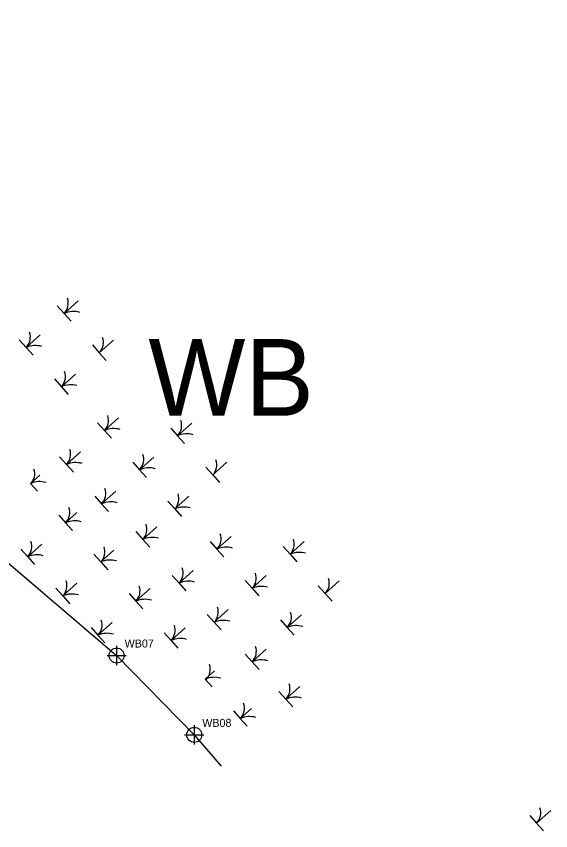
# Model space of a CAD drawing. Extents: x 2126502 to 2127032, y 149550 to 150101.
# Drawn here: x 2126748.5 to 2126915.4, y 149788.3 to 150042.6 of the extents above; entities that cross this region are included whole.
import ezdxf

# ---------------------------------------------------------------- set-up
doc = ezdxf.new("R2010")
doc.units = 0
for name, color, linetype in [('Default', 7, 'Continuous'), ('Exist Environmental Wetland Boundary', 7, 'Continuous'), ('Exist Environmental Wetland Boundary Cogo Number', 7, 'Continuous'), ('Exist Environmental Wetland Boundary Cogo Point CELL', 7, 'Continuous'), ('Exist Hydro Swamp or Marsh', 7, 'Continuous')]:
    doc.layers.add(name, color=color, linetype=linetype)

msp = doc.modelspace()

# ---------------------------------------------------------------- linework, layer by layer
at = {"layer": 'Exist Environmental Wetland Boundary'}
msp.add_lwpolyline([(2126558.24, 150042.64), (2126586.56, 150016.72), (2126627.79, 149984.18), (2126669.56, 149945.39), (2126708.19, 149909.19), (2126734.44, 149881.64), (2126779.81, 149842.99), (2126804.06, 149818.21), (2126812.44, 149808.38)], dxfattribs=at)
at = {"layer": 'Exist Environmental Wetland Boundary Cogo Point CELL'}
for points in [[(2126779.81, 149845.99), (2126779.81, 149842.99)], [(2126776.81, 149842.99), (2126779.81, 149842.99)], [(2126779.81, 149842.99), (2126782.81, 149842.99)], [(2126779.81, 149842.99), (2126779.81, 149839.99)], [(2126804.06, 149821.21), (2126804.06, 149818.21)], [(2126801.06, 149818.21), (2126804.06, 149818.21)], [(2126804.06, 149818.21), (2126807.06, 149818.21)], [(2126804.06, 149818.21), (2126804.06, 149815.21)]]:
    msp.add_lwpolyline(points, dxfattribs=at)
for centre in [(2126779.81, 149842.99), (2126804.06, 149818.21)]:
    msp.add_circle(centre, 2.34, dxfattribs=at)
at = {"layer": 'Exist Hydro Swamp or Marsh'}
for points in [[(2126761.27, 149952.23), (2126763.42, 149949.83), (2126767.83, 149953.78), (2126763.42, 149949.83), (2126765.57, 149947.42)], [(2126749.41, 149941.61), (2126751.56, 149939.21), (2126755.97, 149943.15), (2126751.56, 149939.21), (2126753.72, 149936.8)], [(2126772.24, 149939.98), (2126774.4, 149937.57), (2126778.8, 149941.52), (2126774.4, 149937.57), (2126776.55, 149935.17)], [(2126760.39, 149929.36), (2126762.54, 149926.95), (2126766.95, 149930.9), (2126762.54, 149926.95), (2126764.69, 149924.55)], [(2126773.85, 149915.67), (2126776, 149913.27), (2126780.41, 149917.22), (2126776, 149913.27), (2126778.16, 149910.87)], [(2126796.69, 149914.04), (2126798.84, 149911.64), (2126803.25, 149915.59), (2126798.84, 149911.64), (2126800.99, 149909.24)], [(2126762, 149905.05), (2126764.15, 149902.65), (2126768.56, 149906.6), (2126764.15, 149902.65), (2126766.3, 149900.25)], [(2126784.83, 149903.42), (2126786.98, 149901.02), (2126791.39, 149904.97), (2126786.98, 149901.02), (2126789.13, 149898.61)], [(2126807.66, 149901.79), (2126809.81, 149899.38), (2126814.22, 149903.33), (2126809.81, 149899.38), (2126811.97, 149896.98)], [(2126755.84, 149899.35), (2126752.9, 149896.71), (2126755.05, 149894.31)], [(2126772.97, 149892.8), (2126775.13, 149890.4), (2126779.53, 149894.34), (2126775.13, 149890.4), (2126777.28, 149887.99)], [(2126795.81, 149891.17), (2126797.96, 149888.76), (2126802.37, 149892.71), (2126797.96, 149888.76), (2126800.11, 149886.36)], [(2126761.72, 149886.86), (2126763.88, 149884.46), (2126767.4, 149887.61)], [(2126767.4, 149887.61), (2126763.88, 149884.46), (2126766.03, 149882.06)], [(2126785.83, 149881.67), (2126787.98, 149879.27), (2126792.39, 149883.22), (2126787.98, 149879.27), (2126790.14, 149876.87)], [(2126809, 149878.64), (2126811.15, 149876.24), (2126815.56, 149880.19), (2126811.15, 149876.24), (2126813.3, 149873.83)], [(2126831.83, 149877.01), (2126833.99, 149874.6), (2126838.39, 149878.55), (2126833.99, 149874.6), (2126836.14, 149872.2)], [(2126749.87, 149876.24), (2126752.02, 149873.84), (2126756.43, 149877.79), (2126752.02, 149873.84), (2126754.17, 149871.44)], [(2126772.7, 149874.61), (2126774.85, 149872.21), (2126778.95, 149875.88)], [(2126778.95, 149875.88), (2126774.85, 149872.21), (2126777.01, 149869.8)], [(2126797.14, 149868.02), (2126799.3, 149865.62), (2126803.7, 149869.56), (2126799.3, 149865.62), (2126801.45, 149863.21)], [(2126819.98, 149866.39), (2126822.13, 149863.98), (2126826.54, 149867.93), (2126822.13, 149863.98), (2126824.28, 149861.58)], [(2126842.81, 149864.75), (2126844.96, 149862.35), (2126849.37, 149866.3), (2126844.96, 149862.35), (2126847.12, 149859.95)], [(2126760.85, 149863.99), (2126763, 149861.59), (2126767.41, 149865.54), (2126763, 149861.59), (2126765.15, 149859.18)], [(2126783.68, 149862.36), (2126785.83, 149859.95), (2126790.24, 149863.9), (2126785.83, 149859.95), (2126787.98, 149857.55)], [(2126808.12, 149855.76), (2126810.27, 149853.36), (2126814.68, 149857.31), (2126810.27, 149853.36), (2126812.43, 149850.96)], [(2126830.95, 149854.13), (2126833.11, 149851.73), (2126837.51, 149855.68), (2126833.11, 149851.73), (2126835.26, 149849.33)], [(2126771.82, 149851.74), (2126773.98, 149849.33), (2126778.38, 149853.28), (2126773.98, 149849.33), (2126776.13, 149846.93)], [(2126794.66, 149850.1), (2126796.81, 149847.7), (2126801.22, 149851.65), (2126796.81, 149847.7), (2126798.96, 149845.3)], [(2126820.01, 149843.43), (2126822.17, 149841.02), (2126826.57, 149844.97), (2126822.17, 149841.02), (2126824.32, 149838.62)], [(2126810.41, 149838.22), (2126807.48, 149835.58), (2126809.63, 149833.18)], [(2126830.52, 149831.77), (2126832.67, 149829.37), (2126837.08, 149833.32), (2126832.67, 149829.37), (2126834.83, 149826.97)], [(2126816.3, 149825.73), (2126818.45, 149823.33), (2126821.97, 149826.48)], [(2126821.97, 149826.48), (2126818.45, 149823.33), (2126820.6, 149820.93)], [(2126908.85, 149793.07), (2126911, 149790.67), (2126915.41, 149794.62), (2126911, 149790.67), (2126913.16, 149788.27)]]:
    msp.add_lwpolyline(points, dxfattribs=at)
for centre, radius, start, end in [((2126760.1, 149953.03), 4.61, 315.9957, 19.3903), ((2126766.29, 149943.22), 7.21, 73.9828, 113.4775), ((2126748.25, 149942.41), 4.61, 315.9957, 19.3903), ((2126771.08, 149940.78), 4.61, 315.9957, 19.3903), ((2126754.43, 149932.59), 7.21, 73.9828, 113.4775), ((2126759.22, 149930.16), 4.61, 315.9957, 19.3903), ((2126765.41, 149920.34), 7.21, 73.9828, 113.4775), ((2126772.69, 149916.47), 4.61, 315.9957, 19.3903), ((2126795.52, 149914.84), 4.61, 315.9957, 19.3903), ((2126778.88, 149906.66), 7.21, 73.9828, 113.4775), ((2126801.71, 149905.03), 7.21, 73.9828, 113.4775), ((2126760.83, 149905.85), 4.61, 315.9957, 19.3903), ((2126783.66, 149904.22), 4.61, 315.9957, 19.3903), ((2126806.5, 149902.59), 4.61, 315.9957, 19.3903), ((2126749.61, 149899.69), 4.61, 315.9957, 19.3903), ((2126767.02, 149896.04), 7.21, 73.9828, 113.4775), ((2126789.85, 149894.4), 7.21, 73.9828, 113.4775), ((2126755.77, 149890.1), 7.21, 73.9828, 113.4775), ((2126771.81, 149893.6), 4.61, 315.9957, 19.3903), ((2126794.64, 149891.97), 4.61, 315.9957, 19.3903), ((2126760.56, 149887.66), 4.61, 315.9957, 19.3903), ((2126778, 149883.78), 7.21, 73.9828, 113.4775), ((2126800.83, 149882.15), 7.21, 73.9828, 113.4775), ((2126766.75, 149877.85), 7.21, 73.9828, 113.4775), ((2126784.67, 149882.47), 4.61, 315.9957, 19.3903), ((2126807.84, 149879.44), 4.61, 315.9957, 19.3903), ((2126748.7, 149877.04), 4.61, 315.9957, 19.3903), ((2126790.86, 149872.66), 7.21, 73.9828, 113.4775), ((2126830.67, 149877.81), 4.61, 315.9957, 19.3903), ((2126771.54, 149875.41), 4.61, 315.9957, 19.3903), ((2126814.02, 149869.63), 7.21, 73.9828, 113.4775), ((2126754.89, 149867.23), 7.21, 73.9828, 113.4775), ((2126836.86, 149867.99), 7.21, 73.9828, 113.4775), ((2126777.73, 149865.6), 7.21, 73.9828, 113.4775), ((2126795.98, 149868.82), 4.61, 315.9957, 19.3903), ((2126818.81, 149867.19), 4.61, 315.9957, 19.3903), ((2126759.68, 149864.79), 4.61, 315.9957, 19.3903), ((2126802.17, 149859), 7.21, 73.9828, 113.4775), ((2126841.65, 149865.56), 4.61, 315.9957, 19.3903), ((2126782.51, 149863.16), 4.61, 315.9957, 19.3903), ((2126825, 149857.37), 7.21, 73.9828, 113.4775), ((2126765.87, 149854.97), 7.21, 73.9828, 113.4775), ((2126788.7, 149853.34), 7.21, 73.9828, 113.4775), ((2126806.96, 149856.57), 4.61, 315.9957, 19.3903), ((2126829.79, 149854.93), 4.61, 315.9957, 19.3903), ((2126770.66, 149852.54), 4.61, 315.9957, 19.3903), ((2126813.15, 149846.75), 7.21, 73.9828, 113.4775), ((2126793.49, 149850.9), 4.61, 315.9957, 19.3903), ((2126835.98, 149845.12), 7.21, 73.9828, 113.4775), ((2126776.85, 149842.72), 7.21, 73.9828, 113.4775), ((2126799.68, 149841.09), 7.21, 73.9828, 113.4775), ((2126818.85, 149844.23), 4.61, 315.9957, 19.3903), ((2126804.47, 149838.65), 4.61, 315.9957, 19.3903), ((2126825.04, 149834.41), 7.21, 73.9828, 113.4775), ((2126810.35, 149828.97), 7.21, 73.9828, 113.4775), ((2126829.36, 149832.57), 4.61, 315.9957, 19.3903), ((2126815.14, 149826.54), 4.61, 315.9957, 19.3903), ((2126835.55, 149822.76), 7.21, 73.9828, 113.4775), ((2126821.32, 149816.72), 7.21, 73.9828, 113.4775), ((2126907.69, 149793.88), 4.61, 315.9957, 19.3903)]:
    msp.add_arc(centre, radius, start, end, dxfattribs=at)

# ---------------------------------------------------------------- texts
at = {"layer": 'Default'}
msp.add_text('WB', height=24, dxfattribs=at).set_placement((2126789.73, 149917.85))
at = {"layer": 'Exist Environmental Wetland Boundary Cogo Number'}
for s, p in [('WB07', (2126782.31, 149845.49)), ('WB08', (2126806.56, 149820.71))]:
    msp.add_text(s, height=2.5, dxfattribs=at).set_placement(p)

doc.saveas('drawing.dxf')
